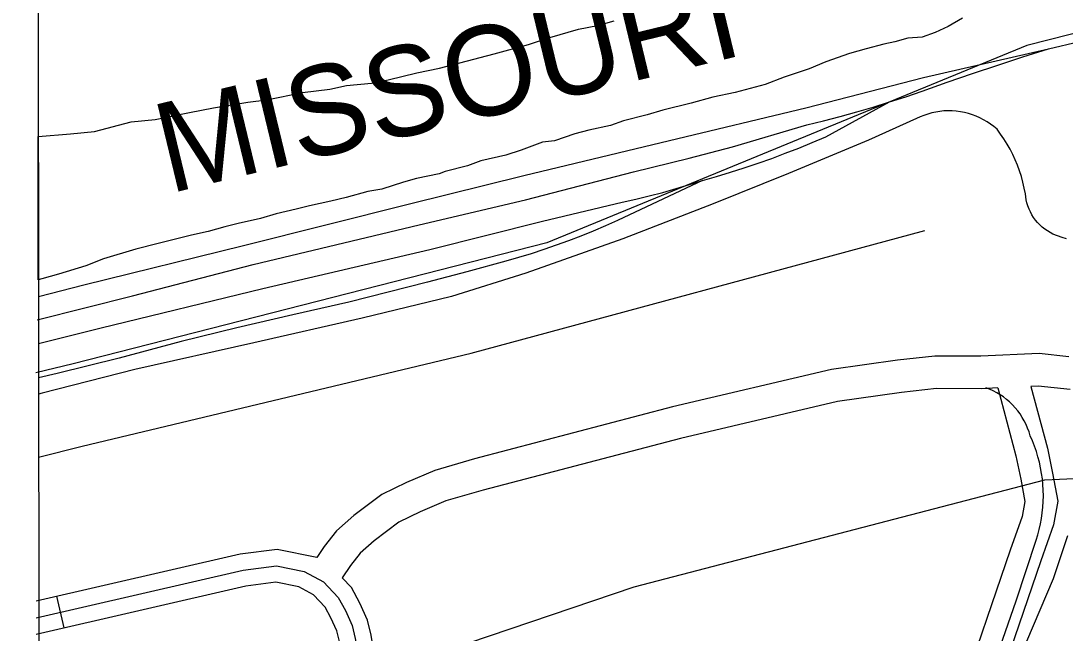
# Model space of a CAD drawing. Extents: x 3313447 to 3351316, y 703786 to 729172.
# Drawn here: x 3317567 to 3318533, y 720470 to 721036 of the extents above; entities that cross this region are included whole.
import ezdxf

# ---------------------------------------------------------------- set-up
doc = ezdxf.new("R2010")
doc.units = 0
for name, color, linetype in [('V-DTCH-CNTR', 7, 'Continuous'), ('V-GRID-FRAM', 7, 'Continuous'), ('V-RAIL-IDEN', 7, 'Continuous'), ('V-RAIL-TRAK', 7, 'Continuous'), ('V-ROAD-CNTR', 7, 'Continuous'), ('V-SITE-OTLN', 7, 'Continuous'), ('V-SITE-VEGE', 7, 'Continuous'), ('V-TOPO-SHOR', 7, 'Continuous')]:
    doc.layers.add(name, color=color, linetype=linetype)

msp = doc.modelspace()

# ---------------------------------------------------------------- linework, layer by layer
at = {"layer": 'V-DTCH-CNTR'}
for points in [[(3318512.09, 720612.48), (3318511.38, 720617.65), (3318510.46, 720622.79), (3318509.34, 720627.89), (3318508.02, 720632.94), (3318506.5, 720637.93), (3318504.78, 720642.86), (3318502.87, 720647.71), (3318500.77, 720652.49), (3318499.71, 720656.03), (3318498.46, 720659.5), (3318497, 720662.9), (3318495.36, 720666.21), (3318493.53, 720669.42), (3318491.52, 720672.52), (3318489.33, 720675.49), (3318486.98, 720678.35), (3318484.47, 720681.06), (3318481.8, 720683.61), (3318479, 720686.02), (3318476.06, 720688.26), (3318473, 720690.33), (3318469.83, 720692.22), (3318466.55, 720693.93), (3318463.18, 720695.45), (3318459.73, 720696.77)], [(3318463.22, 720429.19), (3318487.7, 720499.89), (3318506.33, 720555.83), (3318507.87, 720560.81), (3318509.21, 720565.85), (3318510.35, 720570.95), (3318511.29, 720576.08), (3318512.02, 720581.24), (3318512.55, 720586.44), (3318512.88, 720591.64), (3318512.99, 720596.86), (3318512.9, 720602.08), (3318512.6, 720607.29), (3318512.09, 720612.48)]]:
    msp.add_lwpolyline(points, dxfattribs=at)
at = {"layer": 'V-GRID-FRAM'}
msp.add_lwpolyline([(3317576.91, 727351.01), (3317595.43, 709166.01), (3349105.76, 709211.84), (3349071.38, 727396.82), (3317576.91, 727351.01)], dxfattribs=at)
at = {"layer": 'V-RAIL-TRAK'}
for points in [[(3317582.67, 720759.46), (3317670.75, 720781.8), (3317782.14, 720810.51), (3317935.71, 720847.4), (3318034.2, 720870.44), (3318134.08, 720896.26), (3318185.41, 720908.83), (3318225.63, 720919.29), (3318294.29, 720939.77), (3318309.72, 720943.5), (3318325.08, 720947.48), (3318340.38, 720951.68), (3318355.62, 720956.12), (3318370.79, 720960.8), (3318385.88, 720965.7), (3318400.9, 720970.83), (3318424.11, 720979.04), (3318447.39, 720987.06), (3318470.73, 720994.89), (3318494.14, 721002.53), (3318517.6, 721009.98), (3318546.39, 721016.71), (3318621.96, 721035.52), (3318672.69, 721048.59)], [(3317583.6, 720781.21), (3317625.6, 720791.72), (3317773.3, 720828.24), (3317926.71, 720866.65), (3318032.54, 720893), (3318167.3, 720925.37), (3318293.3, 720955.47), (3318402.18, 720983.34), (3318517.6, 721009.98)], [(3317583.64, 720737.55), (3317641.85, 720752.11), (3317791.08, 720788.55), (3317945.63, 720824.37), (3318049.93, 720850.57), (3318123.6, 720868.33), (3318136.11, 720871.1), (3318148.57, 720874.09), (3318160.98, 720877.31), (3318173.33, 720880.75), (3318185.61, 720884.42), (3318197.83, 720888.3), (3318210.73, 720892), (3318223.58, 720895.9), (3318236.37, 720899.98), (3318249.1, 720904.26), (3318261.76, 720908.73), (3318274.35, 720913.39), (3318286.87, 720918.23), (3318299.32, 720923.26), (3318311.69, 720928.48), (3318370.79, 720960.8)], [(3318197.83, 720888.3), (3318130.21, 720856.49), (3318119.14, 720851.32), (3318107.98, 720846.34), (3318096.73, 720841.56), (3318085.4, 720836.98), (3318073.99, 720832.59), (3318062.51, 720828.41), (3318050.95, 720824.43), (3318039.33, 720820.65), (3318027.64, 720817.08), (3318015.9, 720813.72), (3317979.71, 720803.98), (3317943.48, 720794.44), (3317907.19, 720785.11), (3317870.85, 720775.97), (3317819, 720764.15), (3317767.22, 720751.98), (3317715.54, 720739.47), (3317687, 720731.73), (3317658.4, 720724.21), (3317629.74, 720716.93), (3317601.02, 720709.89), (3317583.68, 720705.78)]]:
    msp.add_lwpolyline(points, dxfattribs=at)
at = {"layer": 'V-ROAD-CNTR'}
msp.add_line((3317607.53, 720474.83), (3317600.79, 720504.06), dxfattribs=at)
for points in [[(3321599.02, 721774.91), (3321486.46, 721744.79), (3321382.66, 721724.41), (3321193.1, 721673.41), (3320900.48, 721603.3), (3320354.97, 721469.44), (3319853.7, 721345.3), (3319482.26, 721260.22), (3319347.64, 721225.14), (3319071.5, 721155.47), (3318801.68, 721085.84), (3318597.17, 721038.41), (3318497.65, 721012.89), (3318053.89, 720830.52), (3317615.85, 720718.78), (3317581.33, 720710.54)], [(3318534.53, 720834.43), (3318530.24, 720835.67), (3318526.02, 720837.1), (3318521.87, 720838.75), (3318519.22, 720840.1), (3318516.66, 720841.63), (3318514.21, 720843.33), (3318511.89, 720845.19), (3318509.69, 720847.2), (3318507.63, 720849.36), (3318505.72, 720851.65), (3318503.97, 720854.06), (3318502.39, 720856.58), (3318500.98, 720859.21), (3318499.74, 720861.92), (3318498.7, 720864.71), (3318497.84, 720867.57), (3318497.18, 720870.47), (3318496.38, 720875.9), (3318495.36, 720881.29), (3318494.12, 720886.64), (3318492.66, 720891.92), (3318490.98, 720897.15), (3318489.09, 720902.3), (3318486.98, 720907.37), (3318484.67, 720912.34), (3318482.16, 720917.22), (3318479.45, 720921.99), (3318476.54, 720926.65), (3318473.44, 720931.18), (3318470.16, 720935.58), (3318467.26, 720938.05), (3318464.22, 720940.35), (3318461.05, 720942.47), (3318457.77, 720944.41), (3318454.38, 720946.15), (3318450.9, 720947.7), (3318447.33, 720949.04), (3318443.69, 720950.18), (3318439.99, 720951.11), (3318436.25, 720951.82), (3318432.47, 720952.32), (3318428.67, 720952.6), (3318424.86, 720952.66), (3318421.05, 720952.5), (3318417.26, 720952.13), (3318413.49, 720951.54), (3318409.77, 720950.73), (3318406.1, 720949.71), (3318402.49, 720948.47), (3318398.96, 720947.04), (3318395.52, 720945.41), (3318351.42, 720925.56), (3318277.35, 720894.79), (3318207.77, 720866.75), (3318124.07, 720834.27), (3318034.51, 720802.51), (3317965.63, 720781.01), (3317882.99, 720760.92), (3317782.8, 720738.12), (3317672.96, 720713.63), (3317587.22, 720691.83), (3317583.69, 720690.92)], [(3318536.51, 720725.48), (3318509.16, 720728.38), (3318455.27, 720725.84), (3318412.68, 720725.93), (3318378.07, 720722.3), (3318317.04, 720713.51), (3318170.15, 720679.12), (3317986.85, 720631.11), (3317950.29, 720620.43), (3317924.15, 720609.32), (3317901.34, 720598.28), (3317875.23, 720578.64), (3317859.3, 720564.46), (3317847.9, 720550.12), (3317841.14, 720539.99)], [(3318470.75, 720696.54), (3318455.94, 720695.84), (3318414.22, 720695.93), (3318381.78, 720692.53), (3318322.61, 720684), (3318177.37, 720650), (3317994.86, 720602.2), (3317960.4, 720592.13), (3317936.56, 720582), (3317917.04, 720572.55), (3317894.25, 720555.41), (3317881.18, 720543.77), (3317872.16, 720532.42), (3317864.55, 720521.03)], [(3318470.75, 720696.54), (3318487.6, 720633.93), (3318492.02, 720612.17), (3318495.92, 720591.81), (3318493.31, 720577.75), (3318482.34, 720546.58), (3318434.46, 720406.98)], [(3318501.43, 720697.98), (3318516.82, 720640.81), (3318521.45, 720617.97), (3318526.45, 720591.91), (3318522.38, 720569.99), (3318510.67, 720536.73), (3318462.19, 720395.36)], [(3318537.89, 720695.16), (3318508.28, 720698.3), (3318501.43, 720697.98)], [(3317841.14, 720539.99), (3317804.47, 720547.39), (3317770.25, 720543.13), (3317581.55, 720499.63)], [(3317581.56, 720484.24), (3317772.87, 720528.34), (3317803.9, 720532.2), (3317829.53, 720527.03), (3317847.21, 720517.47), (3317860.9, 720503.11), (3317867.61, 720490.96), (3317873.83, 720477.09), (3317876.69, 720465.11), (3317879.39, 720448.73), (3317873.76, 720389.97), (3317870.17, 720333.77), (3317866.88, 720276.01), (3317859.25, 720247), (3317856.5, 720228.47), (3317851.68, 720213.7), (3317832.02, 720155.27), (3317744.91, 719935.91), (3317628.37, 719640.31), (3317588.34, 719528.64)], [(3317609.22, 719542.43), (3317642.41, 719635.03), (3317758.86, 719930.39), (3317846.11, 720150.11), (3317865.91, 720208.98), (3317871.15, 720225.02), (3317873.96, 720243.99), (3317881.77, 720273.65), (3317885.15, 720332.87), (3317888.72, 720388.77), (3317894.51, 720449.24), (3317891.4, 720468.08), (3317888.09, 720481.94), (3317881.05, 720497.66), (3317873.1, 720512.06), (3317864.55, 720521.03)], [(3317567.46, 719514.84), (3317614.32, 719645.6), (3317730.96, 719941.43), (3317817.93, 720160.44), (3317837.44, 720218.42), (3317841.85, 720231.92), (3317844.53, 720250.02), (3317851.99, 720278.37), (3317855.2, 720334.68), (3317858.81, 720391.16), (3317864.27, 720448.21), (3317861.98, 720462.15), (3317859.57, 720472.24), (3317854.18, 720484.26), (3317848.71, 720494.17), (3317837.99, 720505.4), (3317824.37, 720512.77), (3317803.33, 720517.02), (3317775.49, 720513.55), (3317581.58, 720468.85)]]:
    msp.add_lwpolyline(points, dxfattribs=at)
at = {"layer": 'V-SITE-OTLN'}
for p, q in [((3318514.28, 720611.56), (3318704.04, 720621.05)), ((3318134.54, 720512.68), (3318514.28, 720611.56)), ((3317634.8, 720344.21), (3318134.54, 720512.68))]:
    msp.add_line(p, q, dxfattribs=at)
at = {"layer": 'V-SITE-VEGE'}
for p, q in [((3318083.13, 721028.13), (3318100.72, 721031.38)), ((3318100.72, 721031.38), (3318116.12, 721035.73)), ((3318425.01, 721030.54), (3318412.91, 721025.07)), ((3318438.22, 721038.2), (3318425.01, 721030.54)), ((3318036.92, 721013.95), (3318056.72, 721020.5)), ((3318056.72, 721020.5), (3318083.13, 721028.13)), ((3318400.8, 721020.7), (3318387.61, 721019.64)), ((3318412.91, 721025.07), (3318400.8, 721020.7)), ((3318005.02, 721005.24), (3318036.92, 721013.95)), ((3318365.61, 721014.2), (3318349.11, 721009.85)), ((3318375.51, 721016.37), (3318365.61, 721014.2)), ((3318387.61, 721019.64), (3318375.51, 721016.37)), ((3317954.42, 720992.18), (3318005.02, 721005.24)), ((3318333.71, 721005.49), (3318311.7, 720997.85)), ((3318349.11, 721009.85), (3318333.71, 721005.49)), ((3317933.52, 720987.84), (3317954.42, 720992.18)), ((3318296.29, 720991.3), (3318273.19, 720983.66)), ((3318311.7, 720997.85), (3318296.29, 720991.3)), ((3317907.12, 720981.31), (3317933.52, 720987.84)), ((3318273.19, 720983.66), (3318255.58, 720977.11)), ((3317827.94, 720969.43), (3317853.23, 720972.66)), ((3317853.23, 720972.66), (3317868.63, 720975.92)), ((3317868.63, 720975.92), (3317891.72, 720978.05)), ((3317891.72, 720978.05), (3317907.12, 720981.31)), ((3318255.58, 720977.11), (3318228.08, 720969.48)), ((3317777.35, 720960.76), (3317794.94, 720962.92)), ((3317794.94, 720962.92), (3317827.94, 720969.43)), ((3318207.18, 720965.14), (3318187.38, 720959.7)), ((3318228.08, 720969.48), (3318207.18, 720965.14)), ((3317723.46, 720951.01), (3317745.45, 720955.35)), ((3317745.45, 720955.35), (3317777.35, 720960.76)), ((3318160.98, 720953.17), (3318146.68, 720948.81)), ((3318187.38, 720959.7), (3318160.98, 720953.17)), ((3317669.57, 720942.36), (3317691.56, 720944.5)), ((3317691.56, 720944.5), (3317723.46, 720951.01)), ((3318124.68, 720943.37), (3318112.58, 720939.01)), ((3318146.68, 720948.81), (3318124.68, 720943.37)), ((3317613.48, 720931.51), (3317635.47, 720933.65)), ((3317635.47, 720933.65), (3317669.57, 720942.36)), ((3318092.78, 720934.66), (3318079.58, 720931.4)), ((3318112.58, 720939.01), (3318092.78, 720934.66)), ((3317583.45, 720928.86), (3317613.48, 720931.51)), ((3317583.58, 720796.51), (3317583.45, 720928.86)), ((3318049.88, 720923.78), (3318030.07, 720916.14)), ((3318060.87, 720924.85), (3318049.88, 720923.78)), ((3318079.58, 720931.4), (3318060.87, 720924.85)), ((3318030.07, 720916.14), (3318015.77, 720911.78)), ((3317992.67, 720906.34), (3317980.56, 720901.97)), ((3318015.77, 720911.78), (3317992.67, 720906.34)), ((3317959.66, 720896.53), (3317954.16, 720894.35)), ((3317980.56, 720901.97), (3317959.66, 720896.53)), ((3317921.16, 720886.74), (3317901.36, 720880.19)), ((3317933.26, 720890.01), (3317921.16, 720886.74)), ((3317954.16, 720894.35), (3317933.26, 720890.01)), ((3317888.16, 720878.03), (3317868.36, 720872.58)), ((3317901.36, 720880.19), (3317888.16, 720878.03)), ((3317854.06, 720869.32), (3317834.26, 720864.98)), ((3317868.36, 720872.58), (3317854.06, 720869.32)), ((3317803.46, 720857.36), (3317789.16, 720853)), ((3317822.16, 720861.71), (3317803.46, 720857.36)), ((3317834.26, 720864.98), (3317822.16, 720861.71)), ((3317768.26, 720848.66), (3317756.16, 720845.39)), ((3317789.16, 720853), (3317768.26, 720848.66)), ((3317725.36, 720837.78), (3317694.56, 720830.16)), ((3317740.76, 720841.04), (3317725.36, 720837.78)), ((3317756.16, 720845.39), (3317740.76, 720841.04)), ((3317694.56, 720830.16), (3317673.66, 720824.72)), ((3317673.66, 720824.72), (3317643.96, 720816)), ((3317627.45, 720809.45), (3317602.15, 720801.82)), ((3317643.96, 720816), (3317627.45, 720809.45)), ((3317602.15, 720801.82), (3317586.75, 720797.46)), ((3317586.75, 720797.46), (3317583.58, 720796.51))]:
    msp.add_line(p, q, dxfattribs=at)
at = {"layer": 'V-TOPO-SHOR'}
for points in [[(3317583.75, 720632.7), (3317624.16, 720642.92), (3317983.86, 720728.59), (3318403.49, 720841.93)], [(3318535.35, 720559.8), (3318522.04, 720520.23), (3318491.22, 720447.95)]]:
    msp.add_lwpolyline(points, dxfattribs=at)

# ---------------------------------------------------------------- texts
at = {"layer": 'V-RAIL-IDEN'}
msp.add_text('MISSOURI', height=83, rotation=13.58291, dxfattribs=at).set_placement((3317704.36, 720875.96))

doc.saveas('drawing.dxf')
